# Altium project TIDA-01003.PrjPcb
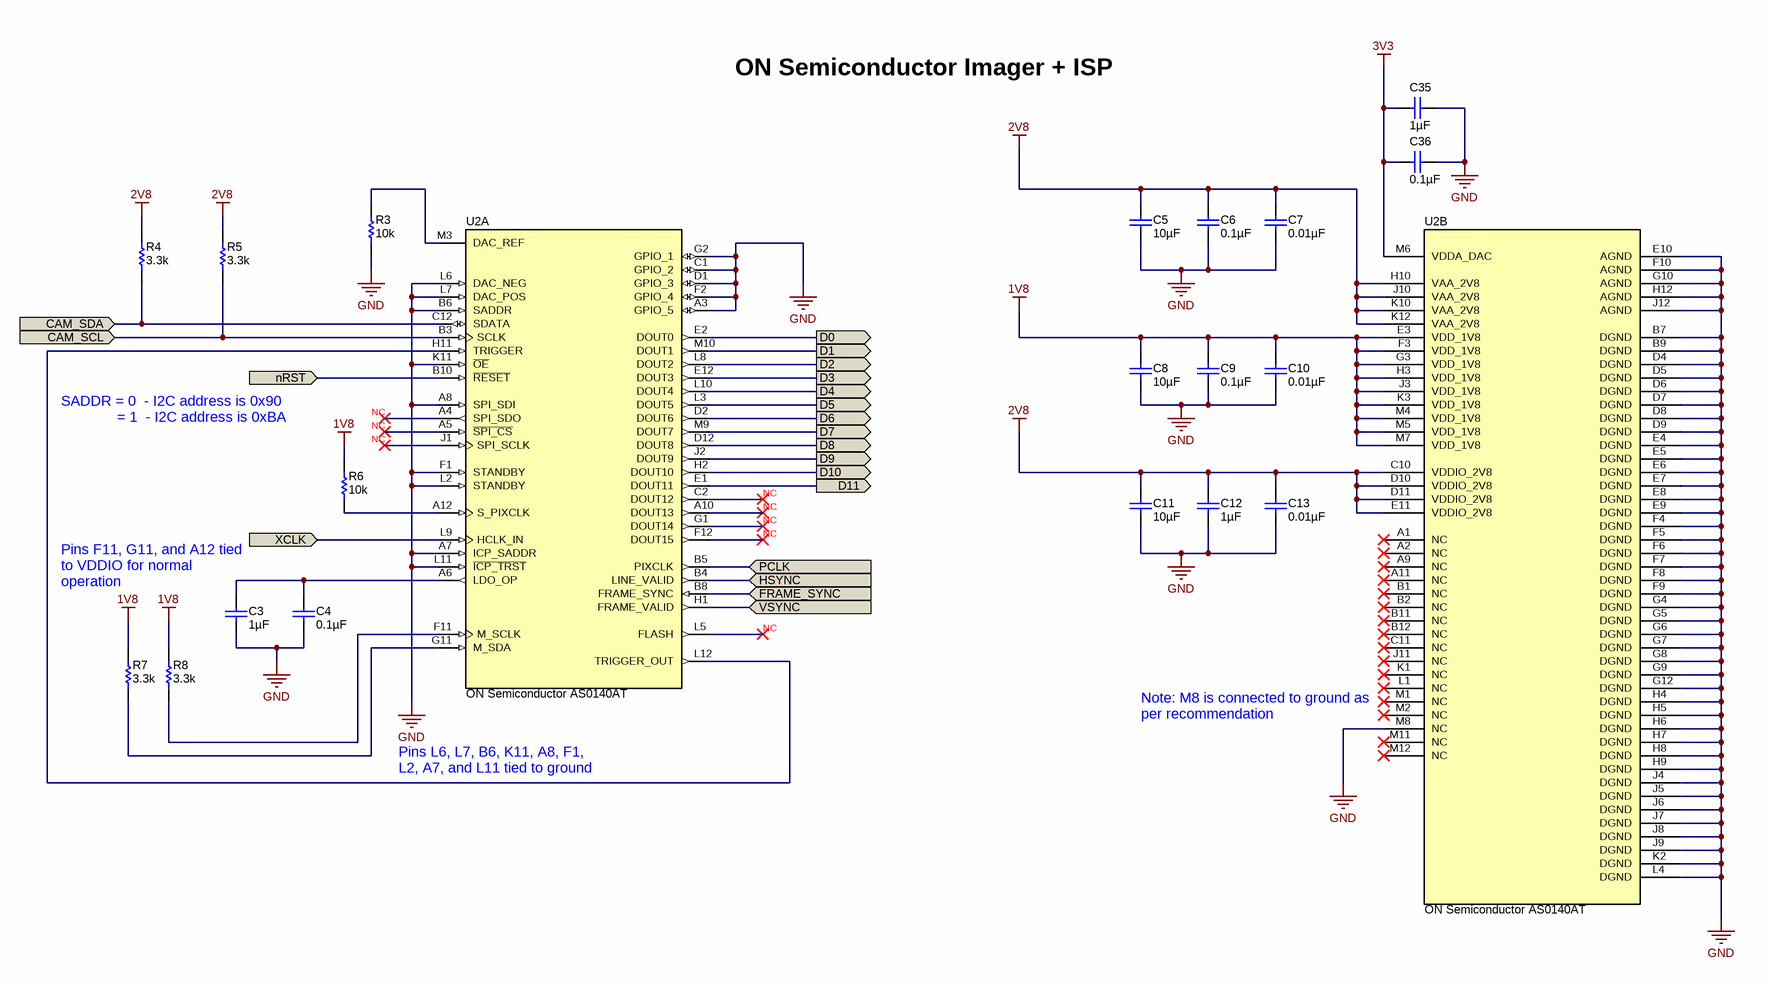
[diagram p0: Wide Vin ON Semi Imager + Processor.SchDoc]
TID: N/A; TechSupport: http://www.ti.com/support; SCH_Rev: E4; PRJ_Title: TIDA-01003-EVM; PRJ_Number: TIDA-01003; PRJ_Engineer: L. CORDOVA; PRJ_Customer: Not Public Release; PCB_Rev: E4; PCB_Layout: L. CORDOVA; CopyrightYear: 2017
5 sheets, 85 parts. Net scope: flat (ports and power ports of the same name join across sheets).
Board file: TIDA-01003.PcbDoc
Sheets:
  Wide Vin ON Semi Imager + Processor.SchDoc
  Wide Vin Power Supply and PoC Filter.SchDoc
  TIDA-01003_EVM_Hardware.SchDoc
  TIDA-01003_CoverSheet.SchDoc
  Wide Vin Serializer.SchDoc

## Sheet Wide Vin ON Semi Imager + Processor.SchDoc
size 431 x 279 mm; Date: Not shown in title block; ApprovedBy: Not shown in title block; CheckedBy: Not shown in title block; Author: Not shown in title block; CompanyName: Not shown in title block; Engineer: Not shown in title block; Organization: Not shown in title block; Address1: Not shown in title block; Address2: Not shown in title block; Address3: Not shown in title block; Address4: Not shown in title block; DocumentNumber: 1; Revision: Use project parameter SCH_Rev; SheetNumber: 4; SheetTotal: 5; PageSetup: Record=PageOptions¦CenterHorizontal=True¦CenterVertical=True¦PrintScale=1.00¦XCorrection=1.00¦YCorrection=1.00¦PrintKind=0¦BorderSize=5000000¦LeftOffset=0¦BottomOffset=0¦Orientation=2¦PaperLength=1000¦PaperWidth=1000¦Scale=100¦PaperSource=15¦PrintQuality=600¦MediaType=1¦DitherType=10¦PaperKind=Letter¦PrintScaleMode=1

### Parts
C3  ValueDisplayed: 1µF  [0402L]  (hidden comment: GRM155R61A105KE15D)
C4  ValueDisplayed: 0.1µF  [0402L]  (hidden comment: GRM155R71C104KA88D)
C5  ValueDisplayed: 10µF  [0805L]  (hidden comment: GRM21BR71A106KE51L)
C6  ValueDisplayed: 0.1µF  [0402L]  (hidden comment: GCM155R71C104KA55D)
C7  ValueDisplayed: 0.01µF  [0402L]  (hidden comment: GRM155R71C103KA01D)
C8  ValueDisplayed: 10µF  [0805L]  (hidden comment: GRM21BR71A106KE51L)
C9  ValueDisplayed: 0.1µF  [0402L]  (hidden comment: GCM155R71C104KA55D)
C10  ValueDisplayed: 0.01µF  [0402L]  (hidden comment: GRM155R71C103KA01D)
C11  ValueDisplayed: 10µF  [0805L]  (hidden comment: GRM21BR71A106KE51L)
C12  ValueDisplayed: 1µF  [0402L]  (hidden comment: GRM155R61A105KE15D)
C13  ValueDisplayed: 0.01µF  [0402L]  (hidden comment: GRM155R71C103KA01D)
C35  ValueDisplayed: 1µF  [0402L]  (hidden comment: GRM155R61A105KE15D)
C36  value 0.1µF  [0402L]  (hidden comment: C1005X7R1E104K050BB)
R3  ValueDisplayed: 10k  [0402L]  (hidden comment: CRCW040210K0JNED)
R4  ValueDisplayed: 3.3k  [0402L]  (hidden comment: CRCW04023K30JNED)
R5  ValueDisplayed: 3.3k  [0402L]  (hidden comment: CRCW04023K30JNED)
R6  ValueDisplayed: 10k  [0402L]  (hidden comment: CRCW040210K0JNED)
R7  ValueDisplayed: 3.3k  [0402L]  (hidden comment: CRCW04023K30JNED)
R8  ValueDisplayed: 3.3k  [0402L]  (hidden comment: CRCW04023K30JNED)
U2  ON Semiconductor AS0140AT  [BGA130_850x850x162]  (parts A,B of 2)

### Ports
CAM_SCL, CAM_SDA, D0 (out), D1 (out), D2 (out), D3 (out), D4 (out), D5 (out), D6 (out), D7 (out), D8 (out), D9 (out), D10 (out), D11 (out), FRAME_SYNC, HSYNC, nRST, PCLK, VSYNC, XCLK

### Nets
1V8: C8.1 C9.1 C10.1 R6.2 R7.2 R8.2 U2.E3(VDD_1V8) U2.F3(VDD_1V8) U2.G3(VDD_1V8) U2.H3(VDD_1V8) U2.J3(VDD_1V8) U2.K3(VDD_1V8) U2.M4(VDD_1V8) U2.M5(VDD_1V8) U2.M7(VDD_1V8)
2V8: C5.1 C6.1 C7.1 C11.1 C12.1 C13.1 R4.2 R5.2 U2.C10(VDDIO_2V8) U2.D10(VDDIO_2V8) U2.D11(VDDIO_2V8) U2.E11(VDDIO_2V8) U2.H10(VAA_2V8) U2.J10(VAA_2V8) U2.K10(VAA_2V8) U2.K12(VAA_2V8)
3V3: C35.1 C36.1 U2.M6(VDDA_DAC)
GND: C3.2 C4.2 C5.2 C6.2 C7.2 C8.2 C9.2 C10.2 C11.2 C12.2 C13.2 C35.2 C36.2 R3.1 U2.A3(GPIO_5) U2.A7(ICP_SADDR) U2.A8(SPI_SDI) U2.B6(SADDR) U2.B7(DGND) U2.B9(DGND) U2.C1(GPIO_2) U2.D1(GPIO_3) U2.D4(DGND) U2.D5(DGND) U2.D6(DGND) U2.D7(DGND) U2.D8(DGND) U2.D9(DGND) U2.E4(DGND) U2.E5(DGND) U2.E6(DGND) U2.E7(DGND) U2.E8(DGND) U2.E9(DGND) U2.E10(AGND) U2.F1(STANDBY) U2.F2(GPIO_4) U2.F4(DGND) U2.F5(DGND) U2.F6(DGND) U2.F7(DGND) U2.F8(DGND) U2.F9(DGND) U2.F10(AGND) U2.G2(GPIO_1) U2.G4(DGND) U2.G5(DGND) U2.G6(DGND) U2.G7(DGND) U2.G8(DGND) U2.G9(DGND) U2.G10(AGND) U2.G12(DGND) U2.H4(DGND) U2.H5(DGND) U2.H6(DGND) U2.H7(DGND) U2.H8(DGND) U2.H9(DGND) U2.H12(AGND) U2.J4(DGND) U2.J5(DGND) U2.J6(DGND) U2.J7(DGND) U2.J8(DGND) U2.J9(DGND) U2.J12(AGND) U2.K2(DGND) U2.K11(~{OE}) U2.L2(STANDBY) U2.L4(DGND) U2.L6(DAC_NEG) U2.L7(DAC_POS) U2.L11(~{ICP_TRST}) U2.M8(NC)
CAM_SCL: R5.1 U2.B3(SCLK) ; port CAM_SCL
CAM_SDA: R4.1 U2.C12(SDATA) ; port CAM_SDA
D0: U2.E2(DOUT0) ; port D0
D1: U2.M10(DOUT1) ; port D1
D2: U2.L8(DOUT2) ; port D2
D3: U2.E12(DOUT3) ; port D3
D4: U2.L10(DOUT4) ; port D4
D5: U2.L3(DOUT5) ; port D5
D6: U2.D2(DOUT6) ; port D6
D7: U2.M9(DOUT7) ; port D7
D8: U2.D12(DOUT8) ; port D8
D9: U2.J2(DOUT9) ; port D9
D10: U2.H2(DOUT10) ; port D10
D11: U2.E1(DOUT11) ; port D11
FRAME_SYNC: U2.B8(FRAME_SYNC) ; port FRAME_SYNC
HSYNC: U2.B4(LINE_VALID) ; port HSYNC
nRST: U2.B10(~{RESET}) ; port nRST
PCLK: U2.B5(PIXCLK) ; port PCLK
VSYNC: U2.H1(FRAME_VALID) ; port VSYNC
XCLK: U2.L9(HCLK_IN) ; port XCLK
NetC3_1: C3.1 C4.1 U2.A6(LDO_OP)
NetR3_2: R3.2 U2.M3(DAC_REF)
NetR6_1: R6.1 U2.A12(S_PIXCLK)
NetR7_1: R7.1 U2.G11(M_SDA)
NetR8_1: R8.1 U2.F11(M_SCLK)
NetU2_H11: U2.H11(TRIGGER) U2.L12(TRIGGER_OUT)

Not connected (* = marked no-connect by the designer): U2 A1(NC)* A2(NC)* A4(SPI_SDO)* A5(~{SPI_CS})* A9(NC)* A10(DOUT13)* A11(NC)* B1(NC)* B2(NC)* B11(NC)* B12(NC)* C2(DOUT12)* C11(NC)* F12(DOUT15)* G1(DOUT14)* J1(SPI_SCLK)* J11(NC)* K1(NC)* L1(NC)* L5(FLASH)* M1(NC)* M2(NC)* M11(NC)* M12(NC)*

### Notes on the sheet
- ON Semiconductor Imager + ISP
- (near R6) SADDR = 0  - I2C address is 0x90
  = 1  - I2C address is 0xBA
- NC
- (near R6) NC
- (near C3) Pins F11, G11, and A12 tied to VDDIO for normal operation
- Note: M8 is connected to ground as per recommendation
- Pins L6, L7, B6, K11, A8, F1, L2, A7, and L11 tied to ground

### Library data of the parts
C3 = GRM155R61A105KE15D: CAP, CERM, 1 µF, 10 V, +/- 10%, X5R, 0402; Manufacturer: MuRata; Polarized: N; CompType: Capacitor; Value: 1uF; U/M: EA; VDC_V: 10; Cap_F: 0.000001; Value1: Unknown; Value2: 10V; TaMin_C: -55; TaMax_C: 85; Cap_Case: 0402; AEC Category: Q200
C4 = GRM155R71C104KA88D: CAP, CERM, 0.1uF, 16V, +/-10%, X7R, 0402; Manufacturer: MuRata; Polarized: N; CompType: Capacitor; U/M: EA; Cap_F: 0.0000001; Tolerance_%: 10; Value1: Unknown; VDC_V: 16; TaMin_C: -55; TaMax_C: 125; Cap_Case: 0402
C5 C8 C11 = GRM21BR71A106KE51L: CAP, CERM, 10uF, 10V, +/-10%, X7R, 0805; Manufacturer: MuRata; Polarized: N; CompType: Capacitor; U/M: EA; Cap_F: 0.00001; Tolerance_%: 10; ESR_Ohm: 0.003; Value1: 0.003 ohm; TaMin_C: -55; TaMax_C: 125; Cap_Case: 0805
C6 C9 = GCM155R71C104KA55D: CAP, CERM, 0.1 µF, 16 V, +/- 10%, X7R, 0402; Manufacturer: MuRata; Value: 0.1uF; VDC_V: 16; Tolerance_%: 10; Polarized: N; CompType: Capacitor; U/M: EA; Cap_F: 0.0000001; Value1: Unknown; Value2: 16V; TaMin_C: -55; TaMax_C: 125; Cap_Case: 0402; SizeArea_mm2: 0.5; SizeAreaWB_mm2: 3; SizeX_mm: 1; SizeZ_mm: 0.6; AEC Category: Q200
C7 C10 C13 = GRM155R71C103KA01D: CAP, CERM, 0.01uF, 16V, +/-10%, X7R, 0402; Manufacturer: MuRata; Polarized: N; CompType: Capacitor; U/M: EA; Cap_F: 0.00000001; Tolerance_%: 10; Value1: Unknown; VDC_V: 16; TaMin_C: -55; TaMax_C: 125; Cap_Case: 0402
C12 C35 = GRM155R61A105KE15D: CAP, CERM, 1 µF, 10 V, +/- 10%, X5R, 0402; Manufacturer: MuRata; Polarized: N; CompType: Capacitor; Value: 1uF; U/M: EA; VDC_V: 10; Cap_F: 0.000001; Value1: Unknown; Value2: 10V; TaMin_C: -55; TaMax_C: 85; Cap_Case: 0402; SizeArea_mm2: 0.5; SizeAreaWB_mm2: 3; SizeX_mm: 1; SizeZ_mm: 0.6; AEC Category: Q200
C36 = C1005X7R1E103K: CAP, CERM, 0.1uF, 25V, +/-10%, X7R, 0402; Manufacturer: TDK Corporation; Tolerance_%: ±10%
R3 R6 = CRCW040210K0JNED: RES, 10 k, 5%, 0.063 W, 0402; Manufacturer: Vishay-Dale; CompType: Resistor; Value: 10k; Res_ohm: 10000; Value_Code: 10k0; Tolerance_%: 5; Power_W: 0.063; Value2: 0.063W; VDC_V: 50; TempCo: 200 ppm/C; EIA_Code: E24; U/M: EA; AEC Category: Q200
R4 R5 R7 R8 = CRCW04023K30JNED: RES, 3.3 k, 5%, 0.063 W, 0402; Manufacturer: Vishay-Dale; CompType: Resistor; Value: 3.3k; Res_ohm: 3300; Value_Code: 3k30; Tolerance_%: 5; Power_W: 0.063; Value2: 0.063W; VDC_V: 50; TempCo: 200 ppm/C; EIA_Code: E24; U/M: EA; AEC Category: Q200
U2 = AS0140: 1MP+ISP Single Package Solution, BGA130; SymbolCreator: Altium

## Sheet Wide Vin Power Supply and PoC Filter.SchDoc
size 431 x 279 mm; Date: Not shown in title block; ApprovedBy: Not shown in title block; CheckedBy: Not shown in title block; Author: Not shown in title block; CompanyName: Not shown in title block; Engineer: Not shown in title block; Organization: Not shown in title block; Address1: Not shown in title block; Address2: Not shown in title block; Address3: Not shown in title block; Address4: Not shown in title block; DocumentNumber: 1; Revision: Use project parameter SCH_Rev; SheetNumber: 2; SheetTotal: 5; PageSetup: Record=PageOptions¦CenterHorizontal=True¦CenterVertical=True¦PrintScale=1.00¦XCorrection=1.00¦YCorrection=1.00¦PrintKind=0¦BorderSize=5000000¦LeftOffset=0¦BottomOffset=0¦Orientation=2¦PaperLength=1000¦PaperWidth=1000¦Scale=100¦PaperSource=15¦PrintQuality=600¦MediaType=1¦DitherType=10¦PaperKind=Letter¦PrintScaleMode=1
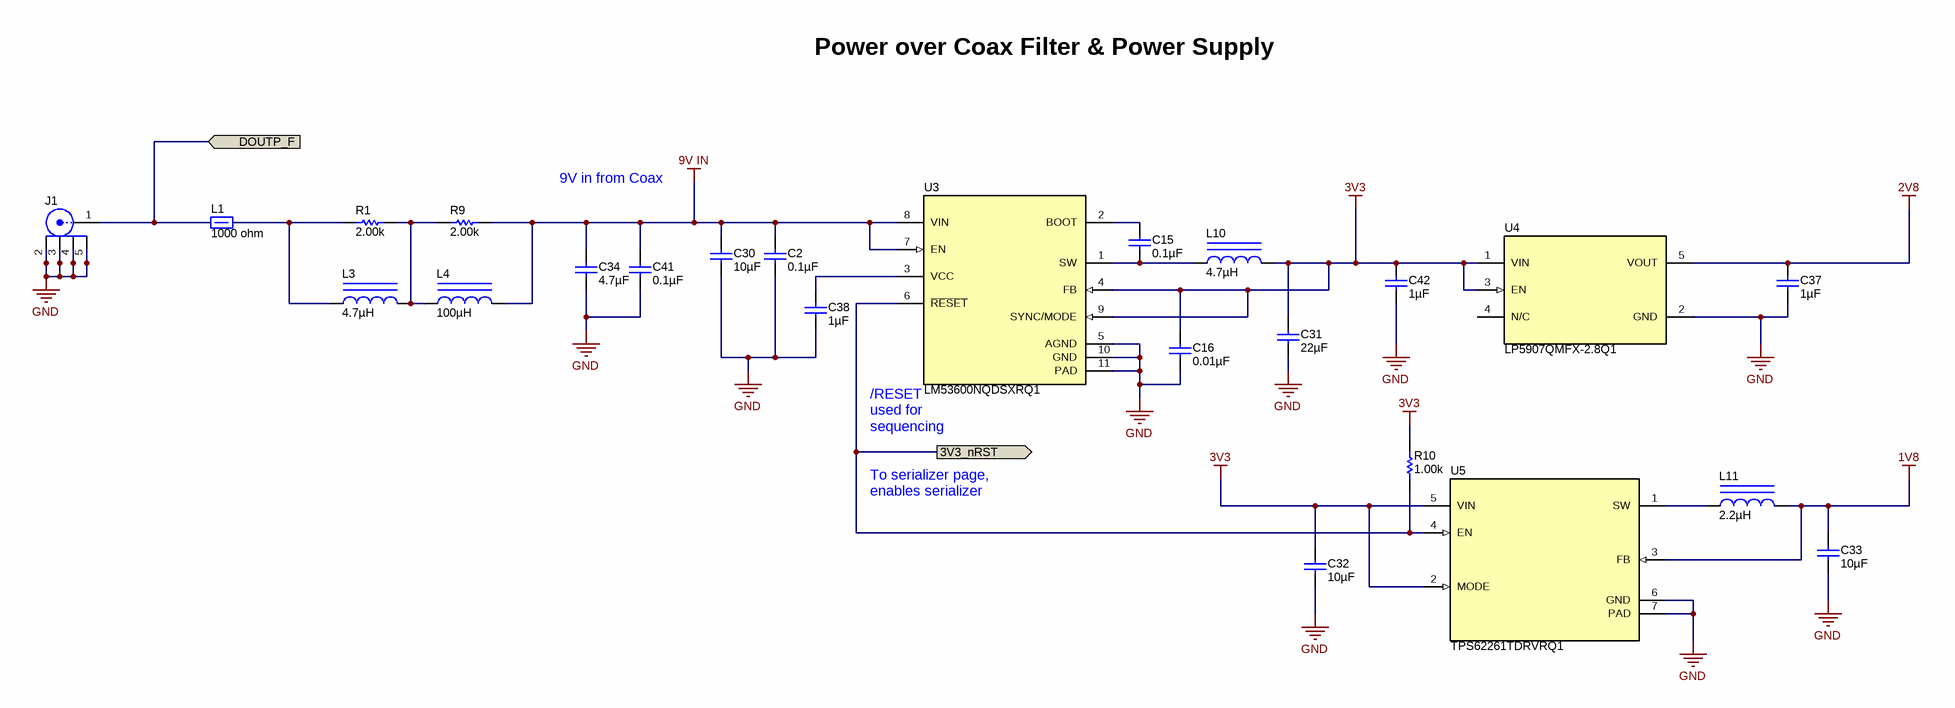
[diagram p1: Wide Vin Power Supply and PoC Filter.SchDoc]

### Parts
C2  ValueDisplayed: 0.1µF  [0402L]  (hidden comment: CGA2B3X7R1H104K050BB)
C15  ValueDisplayed: 0.1µF  [0402L]  (hidden comment: GRM155R71C104KA88D)
C16  ValueDisplayed: 0.01µF  [0402L]  (hidden comment: GRM155R71C103KA01D)
C30  ValueDisplayed: 10µF  [1206_190L]  (hidden comment: CGA5L3X5R1H106K160AB)
C31  ValueDisplayed: 22µF  [0805L]  (hidden comment: CL21B226MQQNNNE)
C32  ValueDisplayed: 10µF  [0805L]  (hidden comment: CL21B106KOQNNNE)
C33  ValueDisplayed: 10µF  [0805L]  (hidden comment: GRM21BR71A106KE51L)
C34  ValueDisplayed: 4.7µF  [0805L]  (hidden comment: CGA4J3X5R1H475M125AB)
C37  ValueDisplayed: 1µF  [0603L]  (hidden comment: LMK107B7105KAHT)
C38  ValueDisplayed: 1µF  [0402L]  (hidden comment: GRM155R61A105KE15D)
C41  ValueDisplayed: 0.1µF  [0402L]  (hidden comment: CGA2B3X7R1H104K050BB)
C42  ValueDisplayed: 1µF  [0603L]  (hidden comment: LMK107B7105KAHT)
J1  59S10H-40ML5-Z  [Rosenberger_59S10H-40ML5-Z]  (value not drawn)
L1  value 1000 ohm  [0402L]  (hidden comment: BLM15AX102SN1D)
L3  ValueDisplayed: 4.7µH  [CBC3225]  (hidden comment: CBC3225T4R7MR)
L4  ValueDisplayed: 100µH  [CBC3225]  (hidden comment: CBC3225T101MR)
L10  ValueDisplayed: 4.7µH  [NRV2010]  (hidden comment: NRV2010T4R7MGF)
L11  ValueDisplayed: 2.2µH  [0805_150]  (hidden comment: MLZ2012M2R2HTD25)
R1  ValueDisplayed: 2.00k  [0402L]  (hidden comment: CRCW04022K00FKED)
R9  ValueDisplayed: 2.00k  [0402L]  (hidden comment: CRCW04022K00FKED)
R10  ValueDisplayed: 1.00k  [0402L]  (hidden comment: CRCW04021K00FKED)
U3  LM53600NQDSXRQ1  [DSX0010A]
U4  LP5907QMFX-2.8Q1  [DBV0005A_N]
U5  TPS62261TDRVRQ1  [DRV0006A]

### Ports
3V3_nRST (out), DOUTP_F

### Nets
1V8: C33.1 L11.2 U5.3(FB)
2V8: C37.1 U4.5(VOUT)
3V3: C16.1 C31.1 C32.1 C42.1 L10.2 R10.2 U3.4(FB) U3.9(SYNC/MODE) U4.1(VIN) U4.3(EN) U5.2(MODE) U5.5(VIN)
9V IN: C2.1 C30.1 C34.1 C41.1 L4.2 R9.1 U3.7(EN) U3.8(VIN)
GND: C2.2 C16.2 C30.2 C31.2 C32.2 C33.2 C34.2 C37.2 C38.2 C41.2 C42.2 J1.2 J1.3 J1.4 J1.5 U3.5(AGND) U3.10(GND) U3.11(PAD) U4.2(GND) U5.6(GND) U5.7(PAD)
3V3_nRST: R10.1 U3.6(~{RESET}) U5.4(EN) ; port 3V3_nRST
DOUTP_F: J1.1 L1.1 ; port DOUTP_F
NetC15_1: C15.1 U3.2(BOOT)
NetC15_2: C15.2 L10.1 U3.1(SW)
NetC38_1: C38.1 U3.3(VCC)
NetL1_2: L1.2 L3.1 R1.2
NetL3_2: L3.2 L4.1 R1.1 R9.2
NetL11_1: L11.1 U5.1(SW)

Not connected (* = marked no-connect by the designer): U4 4(N/C)

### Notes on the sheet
- Power over Coax Filter & Power Supply
- 9V in from Coax
- (near U3) /RESET used for sequencing
- To serializer page, enables serializer

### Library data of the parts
C2 = CGA2B3X7R1H104K050BB: CAP, CERM, 0.1 µF, 50 V, +/- 10%, X7R, AEC-Q200 Grade 1, 0402; Manufacturer: TDK; Value: 0.1uF; VDC_V: 50; Tolerance_%: 10; Polarized: N; CompType: Capacitor; U/M: EA; Cap_F: 0.0000001; Value1: Unknown; Value2: 50V; TaMin_C: -55; TaMax_C: 125; Cap_Case: 0402; AEC Category: Q200; AEC Qualified: Y; AEC Grade: 1
C15 = GRM155R71C104KA88D: CAP, CERM, 0.1 µF, 16 V, +/- 10%, X7R, 0402; Manufacturer: MuRata; Polarized: N; CompType: Capacitor; Value: 0.1uF; U/M: EA; Cap_F: 0.0000001; Tolerance_%: 10; Value1: Unknown; VDC_V: 16; Value2: 16V; TaMin_C: -55; TaMax_C: 125; Cap_Case: 0402; AEC Category: Q200
C16 = GRM155R71C103KA01D: as C7 on sheet Wide Vin ON Semi Imager + Processor
C30 = CGA5L3X5R1H106K160AB: CAP, CERM, 10 µF, 50 V, +/- 10%, X5R, 1206_190; Manufacturer: TDK; Polarized: N; CompType: Capacitor; Value: 10uF; U/M: EA; Cap_F: 0.00001; Tolerance_%: 10; Value1: Unknown; VDC_V: 50; Value2: 50V; TaMin_C: -55; TaMax_C: 85; Cap_Case: 1206; AEC Category: Q200
C31 = CL21B226MQQNNNE: CAP, CERM, 22 µF, 6.3 V, +/- 20%, X7R, 0805; Manufacturer: Samsung Electro-Mechanics; Polarized: N; CompType: Capacitor; Value: 22uF; U/M: EA; Cap_F: 0.000022; Tolerance_%: 20; Value1: Unknown; VDC_V: 6.3; Value2: 6.3V; TaMin_C: -55; TaMax_C: 125; Cap_Case: 0805; AEC Category: Q200; SizeArea_mm2: 2.5; SizeAreaWB_mm2: 6.75; SizeX_mm: 2; SizeY_mm: 1.25; SizeZ_mm: 1.45
C32 = CL21B106KOQNNNE: CAP, CERM, 10 µF, 16 V, +/- 10%, X7R, 0805; Manufacturer: Samsung Electro-Mechanics; Polarized: N; CompType: Capacitor; Value: 10uF; U/M: EA; Cap_F: 0.00001; Tolerance_%: 10; Value1: Unknown; VDC_V: 16; Value2: 16V; TaMin_C: -55; TaMax_C: 125; Cap_Case: 0805; AEC Category: Q200
C33 = GRM21BR71A106KE51L: CAP, CERM, 10 µF, 10 V, +/- 10%, X7R, 0805; Manufacturer: MuRata; Polarized: N; CompType: Capacitor; Value: 10uF; U/M: EA; Cap_F: 0.00001; Tolerance_%: 10; ESR_ohm: 0.003; Value1: 0.003 ohm; Value2: 10V; TaMin_C: -55; TaMax_C: 125; Cap_Case: 0805; AEC Category: Q200
C34 = CGA4J3X5R1H475M125AB: CAP, CERM, 4.7 µF, 50 V, +/- 20%, X5R, AEC-Q200 Grade 3, 0805; Manufacturer: MuRata; Value: 4.7uF; VDC_V: 50; Tolerance_%: 20; Polarized: N; CompType: Capacitor; U/M: EA; Cap_F: 0.0000047; Value1: Unknown; Value2: 50V; TaMin_C: -55; TaMax_C: 85; Cap_Case: 0805; SizeArea_mm2: 2.5; SizeAreaWB_mm2: 6.75; SizeX_mm: 2; SizeY_mm: 1.25; SizeZ_mm: 1.45; AEC Category: Q200; AEC Qualified: Y; AEC Grade: 3
C37 C42 = LMK107B7105KAHT: CAP, CERM, 1 µF, 10 V, +/- 10%, X7R, 0603; Manufacturer: Taiyo Yuden; Polarized: N; CompType: Capacitor; Value: 1uF; U/M: EA; VDC_V: 10; Cap_F: 0.000001; Value1: Unknown; Value2: 10V; TaMin_C: -55; TaMax_C: 125; Cap_Case: 0603; SizeArea_mm2: 1.28; SizeAreaWB_mm2: 4.68; SizeX_mm: 1.6; SizeY_mm: 0.8; SizeZ_mm: 1; AEC Category: Q200; AEC Qualified: Y
C38 = GRM155R61A105KE15D: as C3 on sheet Wide Vin ON Semi Imager + Processor
C41 = CGA2B3X7R1H104K050BB: CAP, CERM, 0.1 µF, 50 V, +/- 10%, X7R, AEC-Q200 Grade 1, 0402; Manufacturer: TDK; Value: 0.1uF; VDC_V: 50; Tolerance_%: 10; Polarized: N; CompType: Capacitor; U/M: EA; Cap_F: 0.0000001; ESR_ohm: 0.039064; Value1: 0.039064 ohm; Value2: 50V; IRMS_A: 0.814669; TaMin_C: -55; TaMax_C: 125; Cap_Case: 0402; SizeArea_mm2: 0.5; SizeAreaWB_mm2: 3; SizeX_mm: 1; SizeZ_mm: 0.6; AEC Category: Q200; AEC Qualified: Y
J1 = 59S10H-40ML5-Z: Connector, HF, 50 Ohm, TH; Manufacturer: Rosenberger; SymbolCreator: X0208326; Gender: Male; ContactFinish: Gold
L1 = BLM15AX102SN1D: Ferrite Bead, 1000 ohm @ 100 MHz, 0.35 A, 0402; Manufacturer: MuRata; Imax_A: 0.35; DCR_ohm: 0.49; Value1: 0.49 ohm; Value2: 0.35A; ZTyp@100MHz_Ohm: 1000
L3 = CBC3225T4R7MR: Inductor, Wirewound, 4.7 µH, 1.01 A, 0.1 ohm, SMD; Manufacturer: Taiyo Yuden; Value: 4.7uH; Ind_H: 4.7E-6; Imax_A: 1.01; Irms: 1.04A @ 40C rise; Isat: 1.25A @ 30% inductance drop; DCR_ohm: 0.1; Value1: 0.1 ohm; Value2: 1.01A; AEC Category: Q200; AEC Qualified: N; SizeAreaWB_mm2: 14.7; SizeArea_mm2: 8; SizeX_mm: 3.2; SizeY_mm: 2.5; SizeZ_mm: 2.7; Green_Lifecycle: Active; Green_REACh: Passed
L4 = CBC3225T101MR: Inductor, Wirewound, 100 µH, 0.27 A, 1.4 ohm, SMD; Manufacturer: Taiyo Yuden; Value: 100uH; Ind_H: 100.0E-6; Imax_A: 0.27; Irms: 0.34A @ 40C rise; Isat: 0.27A @ 30% inductance drop; DCR_ohm: 1.4; Value1: 1.4 ohm; Value2: 0.27A; AEC Category: Q200; AEC Qualified: N; SizeAreaWB_mm2: 14.7; SizeArea_mm2: 8; SizeX_mm: 3.2; SizeY_mm: 2.5; SizeZ_mm: 2.7; Green_Lifecycle: Active; Green_REACh: Passed
L10 = NRV2010T4R7MGF: Inductor, Wirewound, Ferrite, 4.7 µH, 0.76 A, 0.384 ohm, SMD; Manufacturer: Taiyo Yuden; Value: 4.7uH; Ind_H: 4.7E-6; Imax_A: 0.76; Irms: 0.82A @ 40C rise; Isat: 0.76A @ 30% inductance drop; DCR_ohm: 0.384; Value2: 0.76A; AEC Category: Q200
L11 = MLZ2012M2R2HTD25: Inductor, Multilayer, Ferrite, 2.2 µH, 0.4 A, 0.16 ohm, AEC-Q200 Grade 1, SMD; Manufacturer: TDK; Value: 2.2uH; Ind_H: 2.2E-6; Imax_A: 0.4; Irms: 0.6A @ 20C rise; Isat: 0.4A @ 50% inductance drop; DCR_ohm: 0.16; Value2: 0.4A; AEC Category: Q200; AEC Qualified: Y; AEC Grade: 1
R1 R9 = CRCW04022K00FKED: RES, 2.00 k, 1%, 0.063 W, 0402; Manufacturer: Vishay-Dale; CompType: Resistor; Value: 2.00k; Res_ohm: 2000; Value_Code: 2k00; Tolerance_%: 1; Power_W: 0.063; Value2: 0.063W; VDC_V: 50; TempCo: 100 ppm/C; EIA_Code: E96; U/M: EA; AEC Category: Q200
R10 = CRCW04021K00FKED: RES, 1.00 k, 1%, 0.063 W, 0402; Manufacturer: Vishay-Dale; CompType: Resistor; Value: 1.00k; Res_ohm: 1000; Value_Code: 1k00; Tolerance_%: 1; Power_W: 0.063; Value2: 0.063W; VDC_V: 50; TempCo: 100 ppm/C; EIA_Code: E96; U/M: EA; SizeArea_mm2: 0.5; SizeZ_mm: 0.6; AEC Category: Q200
U3 = LM53600NQDSXRQ1: Synchronous Buck Regulator for 650mA Space Constraint Applications, DSX0010A; Manufacturer: Texas Instruments; SymbolCreator: Altium; SizeX_mm: 3; SizeZ_mm: 0.8; CompType: IC; U/M: EA
U4 = LP5907QMFX-2.8Q1: Automotive 250-mA, Ultra-Low-Noise, Low-IQ LDO, DBV0005A (SOT-5); Manufacturer: Texas Instruments; SymbolCreator: a0799628; SizeArea_mm2: 8.12; SizeAreaWB_mm2: 14.82; SizeX_mm: 2.8; SizeY_mm: 2.9; SizeZ_mm: 1.45; CompType: IC; U/M: EA
U5 = TPS62261TDRVRQ1: 2.25-MHz 600-mA STEP-DOWN CONVERTER, DRV0006A; Manufacturer: Texas Instruments; SymbolCreator: Altium; SizeX_mm: 2; SizeZ_mm: 0.8; CompType: IC; U/M: EA

## Sheet TIDA-01003_EVM_Hardware.SchDoc
size 431 x 279 mm; Date: Not shown in title block; ApprovedBy: Not shown in title block; CheckedBy: Not shown in title block; Author: Not shown in title block; CompanyName: Not shown in title block; Engineer: Not shown in title block; Organization: Not shown in title block; Address1: Not shown in title block; Address2: Not shown in title block; Address3: Not shown in title block; Address4: Not shown in title block; DocumentNumber: 1; Revision: Use project parameter SCH_Rev; SheetNumber: 5; SheetTotal: 5; PageSetup: Record=PageOptions¦CenterHorizontal=True¦CenterVertical=True¦PrintScale=1.00¦XCorrection=1.00¦YCorrection=1.00¦PrintKind=0¦BorderSize=5000000¦LeftOffset=0¦BottomOffset=0¦Orientation=2¦PaperLength=1000¦PaperWidth=1000¦Scale=100¦PaperSource=15¦PrintQuality=600¦MediaType=1¦DitherType=10¦PaperKind=Letter¦PrintScaleMode=1
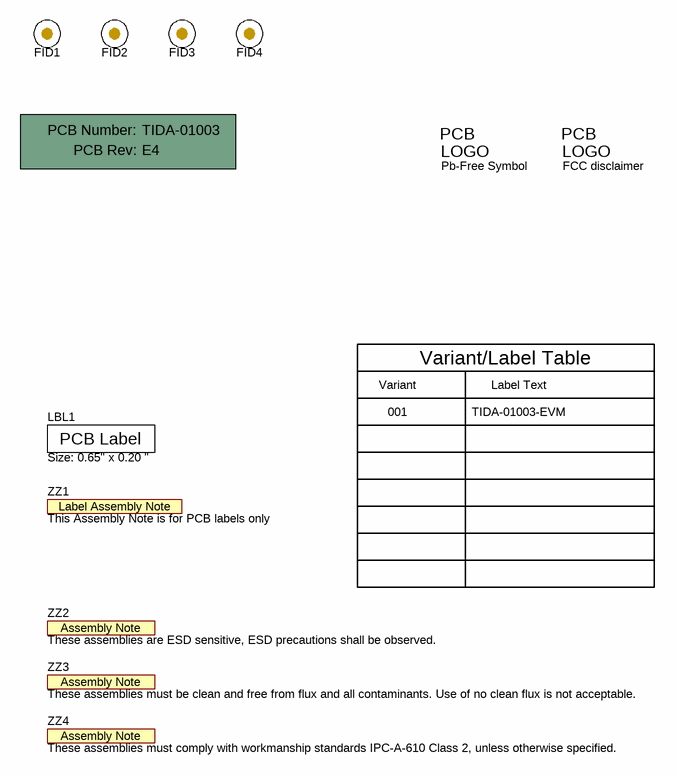
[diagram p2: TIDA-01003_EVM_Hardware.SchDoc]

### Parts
!PCB  Printed Circuit Board  (value not drawn)  (mechanical)
FID1  Fiducial  [Fiducial10-20]  (value not drawn)
FID2  Fiducial  [Fiducial10-20]  (value not drawn)
FID3  Fiducial  [Fiducial10-20]  (value not drawn)
FID4  Fiducial  [Fiducial10-20]  (value not drawn)
LBL1  Size: 0.65" x 0.20 "  [Label_650x200]
Logo2  Pb-Free Symbol  [Pb-Free_Overlay_Small]  (no BOM)
Logo3  FCC disclaimer  [FCC_disclaimer_stacked]  (no BOM)
ZZ1  This Assembly Note is for PCB labels only  [AssemblyNoteLabel]  (no BOM)
ZZ2  These assemblies are ESD sensitive, ESD precautions shall be observed.  [AssemblyNote]  (no BOM)
ZZ3  These assemblies must be clean and free from flux and all contaminants. Use of no clean flux is not acceptable.  [AssemblyNote]  (no BOM)
ZZ4  These assemblies must comply with workmanship standards IPC-A-610 Class 2, unless otherwise specified.  [AssemblyNote]  (no BOM)

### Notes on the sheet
- Variant
- Variant/Label Table
- Label Text
- 001
- TIDA-01003-EVM

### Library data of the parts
!PCB = PCB: Manufacturer: Any; PartNumber: TIDA-01003; SymbolCreator: a0412235
FID1-FID4 = Fiducial: Fiducial mark.  There is nothing to buy or mount.; SymbolCreator: codlsc
LBL1 = THT-14-423-10: Thermal Transfer Printable Labels, 0.650" W x 0.200" H - 10,000 per roll; Manufacturer: Brady; SymbolCreator: a0412235; CompType: Label
Logo2 = Pb-Free: SymbolCreator: a0412235
Logo3 = FCC_disclaimer: SymbolCreator: codlsc
ZZ1 = AssemblyNoteLabel: SymbolCreator: a0412235
ZZ2-ZZ4 = AssemblyNote: SymbolCreator: codlsc

## Sheet TIDA-01003_CoverSheet.SchDoc
size 431 x 279 mm; Date: Not shown in title block; ApprovedBy: Not shown in title block; CheckedBy: Not shown in title block; Author: Not shown in title block; CompanyName: Not shown in title block; Engineer: Not shown in title block; Organization: Not shown in title block; Address1: Not shown in title block; Address2: Not shown in title block; Address3: Not shown in title block; Address4: Not shown in title block; DocumentNumber: 1; Revision: Use project parameter SCH_Rev; SheetNumber: 1; SheetTotal: 5; PageSetup: Record=PageOptions¦CenterHorizontal=True¦CenterVertical=True¦PrintScale=1.00¦XCorrection=1.00¦YCorrection=1.00¦PrintKind=0¦BorderSize=5000000¦LeftOffset=0¦BottomOffset=0¦Orientation=2¦PaperLength=1000¦PaperWidth=1000¦Scale=100¦PaperSource=15¦PrintQuality=600¦MediaType=1¦DitherType=10¦PaperKind=Letter¦PrintScaleMode=1
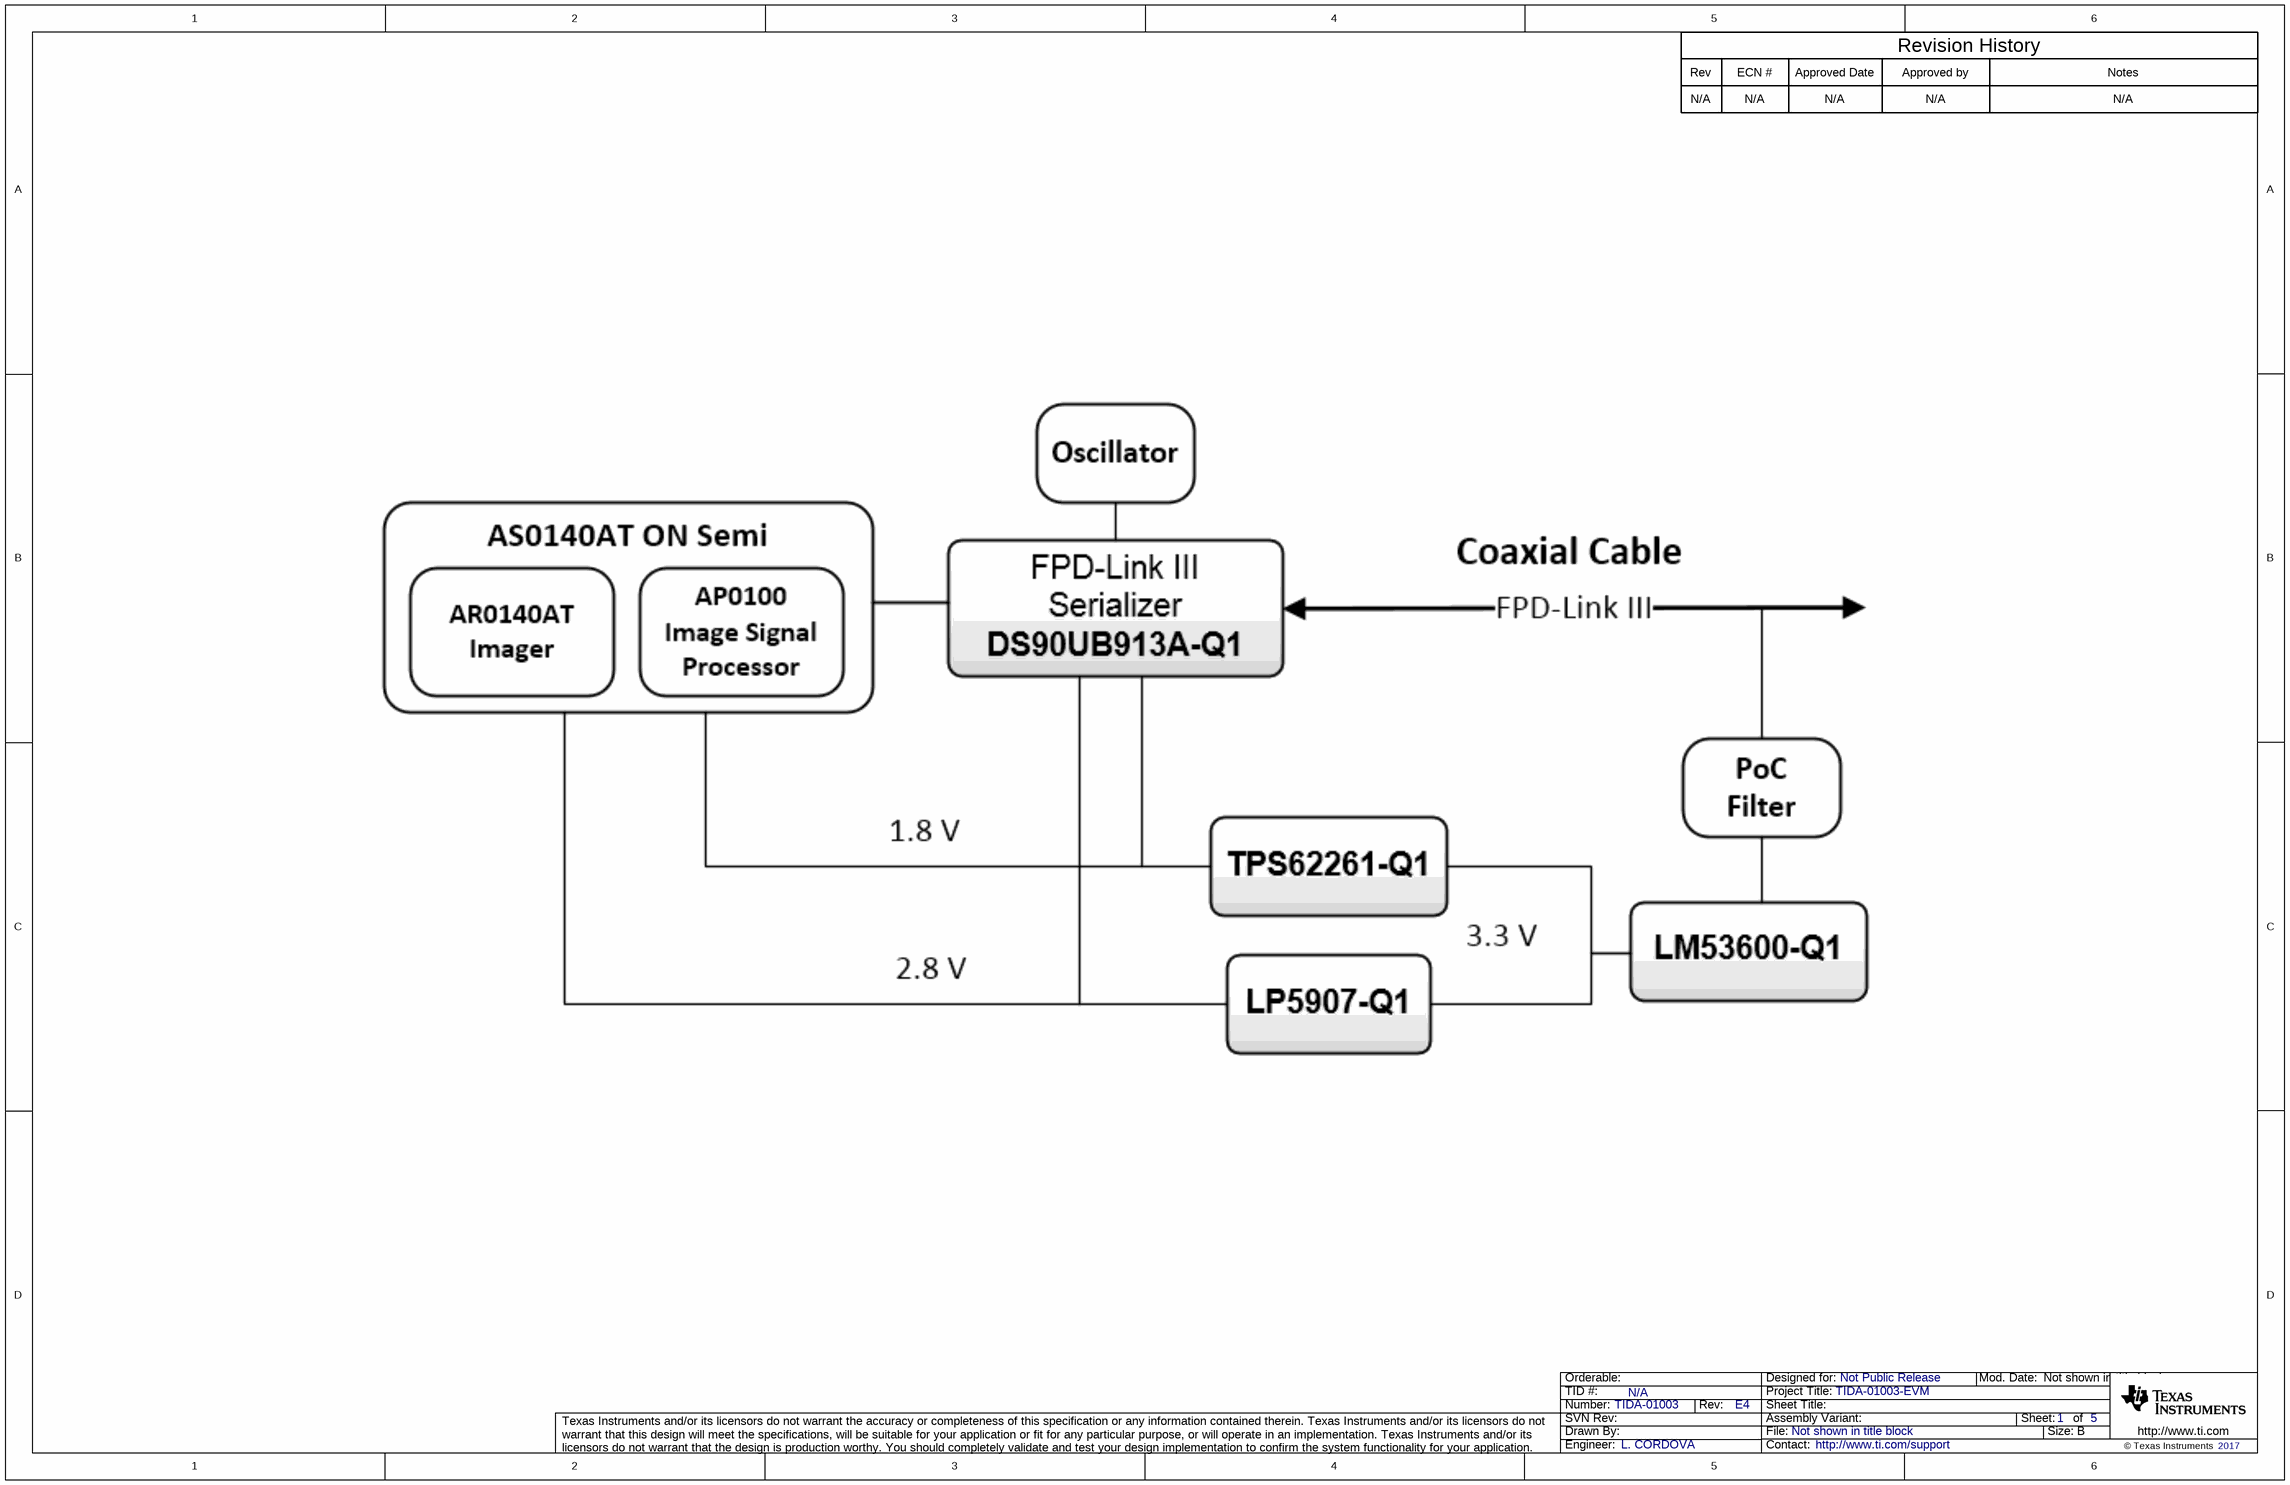
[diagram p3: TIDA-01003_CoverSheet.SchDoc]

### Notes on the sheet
- Rev
- N/A
- ECN #
- Approved Date
- Approved by
- Revision History
- Notes

## Sheet Wide Vin Serializer.SchDoc
size 431 x 279 mm; Date: Not shown in title block; ApprovedBy: Not shown in title block; CheckedBy: Not shown in title block; Author: Not shown in title block; CompanyName: Not shown in title block; Engineer: Not shown in title block; Organization: Not shown in title block; Address1: Not shown in title block; Address2: Not shown in title block; Address3: Not shown in title block; Address4: Not shown in title block; DocumentNumber: 1; Revision: Use project parameter SCH_Rev; SheetNumber: 3; SheetTotal: 5; PageSetup: Record=PageOptions¦CenterHorizontal=True¦CenterVertical=True¦PrintScale=1.00¦XCorrection=1.00¦YCorrection=1.00¦PrintKind=0¦BorderSize=5000000¦LeftOffset=0¦BottomOffset=0¦Orientation=2¦PaperLength=1000¦PaperWidth=1000¦Scale=100¦PaperSource=15¦PrintQuality=600¦MediaType=1¦DitherType=10¦PaperKind=Letter¦PrintScaleMode=1
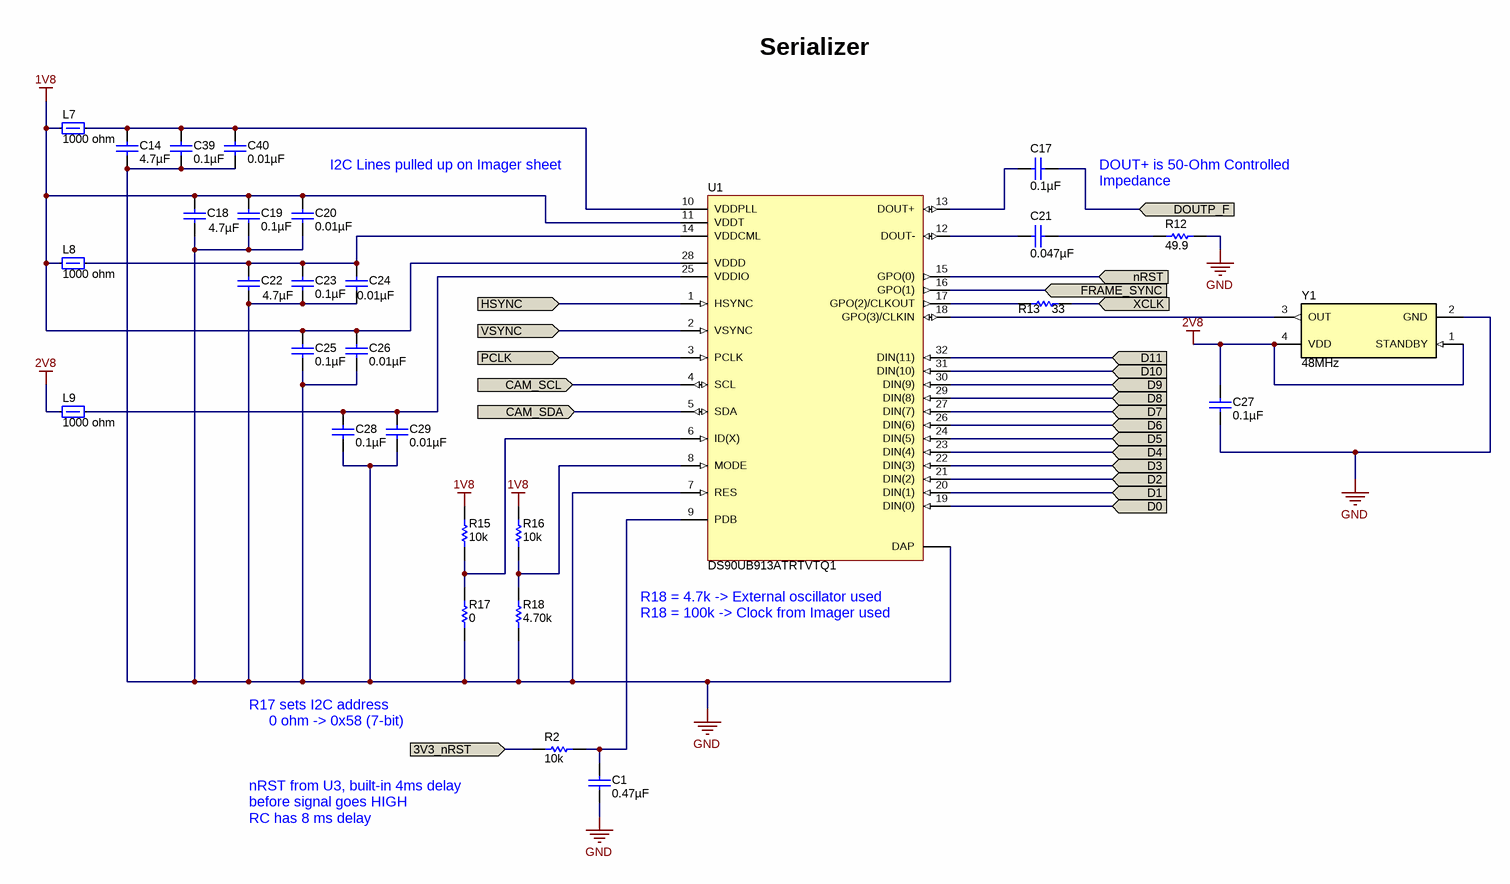
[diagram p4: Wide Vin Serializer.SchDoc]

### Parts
C1  ValueDisplayed: 0.47µF  [0603L]  (hidden comment: C1608X7R1H474K080AC)
C14  ValueDisplayed: 4.7µF  [0603L]  (hidden comment: JMK107BB7475MA-T)
C17  ValueDisplayed: 0.1µF  [0402L]  (hidden comment: CGA2B3X7R1H104K050BB)
C18  value 4.7µF  [0603L]  (hidden comment: CL10B475KQ8NQNC)
C19  ValueDisplayed: 0.1µF  [0402L]  (hidden comment: GRM155R71C104KA88D)
C20  ValueDisplayed: 0.01µF  [0402L]  (hidden comment: GRM155R71C103KA01D)
C21  ValueDisplayed: 0.047µF  [0402L]  (hidden comment: CGA2B3X7R1H473K050BB)
C22  value 4.7µF  [0603L]  (hidden comment: CL10B475KQ8NQNC)
C23  ValueDisplayed: 0.1µF  [0402L]  (hidden comment: GRM155R71C104KA88D)
C24  ValueDisplayed: 0.01µF  [0402L]  (hidden comment: GRM155R71C103KA01D)
C25  ValueDisplayed: 0.1µF  [0402L]  (hidden comment: GRM155R71C104KA88D)
C26  ValueDisplayed: 0.01µF  [0402L]  (hidden comment: GRM155R71C103KA01D)
C27  ValueDisplayed: 0.1µF  [0402L]  (hidden comment: GRM155R71C104KA88D)
C28  ValueDisplayed: 0.1µF  [0402L]  (hidden comment: GRM155R71C104KA88D)
C29  ValueDisplayed: 0.01µF  [0402L]  (hidden comment: GRM155R71C103KA01D)
C39  ValueDisplayed: 0.1µF  [0402L]  (hidden comment: GRM155R71C104KA88D)
C40  ValueDisplayed: 0.01µF  [0402L]  (hidden comment: GRM155R71C103KA01D)
L7  value 1000 ohm  [0402L]  (hidden comment: BLM15AX102SN1D)
L8  value 1000 ohm  [0402L]  (hidden comment: BLM15AX102SN1D)
L9  value 1000 ohm  [0402L]  (hidden comment: BLM15AX102SN1D)
R2  value 10k  [0402L]  (hidden comment: CRCW040210K0JNED)
R12  value 49.9  [0402L]  (hidden comment: CRCW040249R9FKED)
R13  value 33  [0402L]  (hidden comment: CRCW040233R0JNED)
R15  value 10k  [0402L]  (hidden comment: CRCW040210K0JNED)
R16  value 10k  [0402L]  (hidden comment: CRCW040210K0JNED)
R17  value 0  [0402L]  (hidden comment: CRCW04020000Z0ED)
R18  ValueDisplayed: 4.70k  [0402L]  (hidden comment: CRG0402F4K7)
U1  DS90UB913ATRTVTQ1  [RTV0032A]
Y1  Frequency: 48MHz  [Abracon_ASDMB]  (hidden comment: ASDMB-48.000MHZ-LY-T)

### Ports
3V3_nRST (in), CAM_SCL, CAM_SDA, D0, D1, D2, D3, D4, D5, D6, D7, D8, D9, D10, D11, DOUTP_F, FRAME_SYNC, HSYNC, nRST, PCLK, VSYNC, XCLK

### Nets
1V8: C18.1 C19.1 C20.1 C25.1 C26.1 L7.1 L8.1 R15.2 R16.2 U1.11(VDDT) U1.28(VDDD)
2V8: C27.1 L9.1 Y1.1(STANDBY) Y1.4(VDD)
GND: C1.2 C14.2 C18.2 C19.2 C20.2 C22.2 C23.2 C24.2 C25.2 C26.2 C27.2 C28.2 C29.2 C39.2 C40.2 R12.2 R17.1 R18.1 U1.7(RES) U1.33(DAP) Y1.2(GND)
3V3_nRST: R2.2 ; port 3V3_nRST
CAM_SCL: U1.4(SCL) ; port CAM_SCL
CAM_SDA: U1.5(SDA) ; port CAM_SDA
D0: U1.19(DIN(0)) ; port D0
D1: U1.20(DIN(1)) ; port D1
D2: U1.21(DIN(2)) ; port D2
D3: U1.22(DIN(3)) ; port D3
D4: U1.23(DIN(4)) ; port D4
D5: U1.24(DIN(5)) ; port D5
D6: U1.26(DIN(6)) ; port D6
D7: U1.27(DIN(7)) ; port D7
D8: U1.29(DIN(8)) ; port D8
D9: U1.30(DIN(9)) ; port D9
D10: U1.31(DIN(10)) ; port D10
D11: U1.32(DIN(11)) ; port D11
DOUTP_F: C17.1 ; port DOUTP_F
FRAME_SYNC: U1.16(GPO(1)) ; port FRAME_SYNC
HSYNC: U1.1(HSYNC) ; port HSYNC
nRST: U1.15(GPO(0)) ; port nRST
PCLK: U1.3(PCLK) ; port PCLK
VSYNC: U1.2(VSYNC) ; port VSYNC
XCLK: R13.2 ; port XCLK
NetC1_1: C1.1 R2.1 U1.9(PDB)
NetC14_1: C14.1 C39.1 C40.1 L7.2 U1.10(VDDPLL)
NetC17_2: C17.2 U1.13(DOUT+)
NetC21_1: C21.1 R12.1
NetC21_2: C21.2 U1.12(DOUT-)
NetC22_1: C22.1 C23.1 C24.1 L8.2 U1.14(VDDCML)
NetC28_1: C28.1 C29.1 L9.2 U1.25(VDDIO)
NetR13_1: R13.1 U1.17(GPO(2)/CLKOUT)
NetR15_1: R15.1 R17.2 U1.6(ID(X))
NetR16_1: R16.1 R18.2 U1.8(MODE)
NetU1_18: U1.18(GPO(3)/CLKIN) Y1.3(OUT)

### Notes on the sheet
- Serializer
- (near C20) I2C Lines pulled up on Imager sheet
- DOUT+ is 50-Ohm Controlled Impedance
- (near U1) R18 = 4.7k -> External oscillator used
  R18 = 100k -> Clock from Imager used
- R17 sets I2C address
  0 ohm -> 0x58 (7-bit)
- (near R2) nRST from U3, built-in 4ms delay before signal goes HIGH
  RC has 8 ms delay

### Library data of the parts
C1 = C1608X7R1H474K080AC: CAP, CERM, 0.47 µF, 50 V, +/- 10%, X7R, 0603; Manufacturer: TDK; Polarized: N; CompType: Capacitor; Value: 0.47uF; U/M: EA; Cap_F: 0.00000047; Tolerance_%: 10; ESR_ohm: 0.010974; Value1: 0.010974 ohm; VDC_V: 50; Value2: 50V; IRMS_A: 1.57483; TaMin_C: -55; TaMax_C: 125; Cap_Case: 0603; SizeArea_mm2: 1.28; SizeAreaWB_mm2: 4.68; SizeX_mm: 1.6; SizeY_mm: 0.8; SizeZ_mm: 1; AEC Category: Q200
C14 = JMK107BB7475MA-T: CAP, CERM, 4.7 µF, 6.3 V, +/- 10%, X7R, 0603; Manufacturer: Taiyo Yuden; Polarized: N; CompType: Capacitor; Value: 4.7uF; U/M: EA; Cap_F: 0.0000047; Tolerance_%: 10; Value1: Unknown; VDC_V: 6.3; Value2: 6.3V; TaMin_C: -55; TaMax_C: 125; Cap_Case: 0603; AEC Category: Q200
C17 = CGA2B3X7R1H104K050BB: CAP, CERM, 0.1 µF, 50 V, +/- 10%, X7R, AEC-Q200 Grade 1, 0402; Manufacturer: TDK; Polarized: N; CompType: Capacitor; Value: 0.1uF; U/M: EA; Cap_F: 0.0000001; Tolerance_%: 10; ESR_ohm: 0.039064; Value1: 0.039064 ohm; VDC_V: 50; Value2: 50V; IRMS_A: 0.814669; TaMin_C: -55; TaMax_C: 125; Cap_Case: 0402; SizeArea_mm2: 0.5; SizeAreaWB_mm2: 3; SizeX_mm: 1; SizeZ_mm: 0.6; AEC Category: Q200; AEC Qualified: Y
C18 C22 = Capacitor: CAP CER 4.7UF 6.3V 10% X7R 0603; Manufacturer: Samsung Electro-Mechanics America, Inc; Polarized: N; U/M: EA
C19 C23 C25 C27 C28 = GRM155R71C104KA88D: as C4 on sheet Wide Vin ON Semi Imager + Processor
C20 C24 C26 C29 C40 = GRM155R71C103KA01D: as C7 on sheet Wide Vin ON Semi Imager + Processor
C21 = CGA2B3X7R1H473K050BB: CAP, CERM, 0.047 µF, 50 V, +/- 10%, X7R, AEC-Q200 Grade 1, 0402; Manufacturer: TDK; Polarized: N; CompType: Capacitor; Value: 0.047uF; U/M: EA; Cap_F: 0.000000047; Tolerance_%: 10; ESR_ohm: 0.06407; Value1: 0.06407 ohm; VDC_V: 50; Value2: 50V; IRMS_A: 0.646122; TaMin_C: -55; TaMax_C: 125; Cap_Case: 0402; SizeArea_mm2: 0.5; SizeAreaWB_mm2: 3; SizeX_mm: 1; SizeZ_mm: 0.6; AEC Category: Q200; AEC Qualified: Y
C39 = GRM155R71C104KA88D: as C15 on sheet Wide Vin Power Supply and PoC Filter
L7-L9 = BLM15AX102SN1D: as L1 on sheet Wide Vin Power Supply and PoC Filter
R2 R15 R16 = CRCW040210K0JNED: RES, 10k ohm, 5%, 0.063W, 0402; Manufacturer: Vishay-Dale; CompType: Resistor; Res_ohm: 10000; Value_Code: 10k0; Tolerance_%: 5; Power_W: 0.063; VDC_V: 50; TempCo: 200 ppm/C; EIA_Code: E24; U/M: EA
R12 = CRCW040249R9FKED: RES, 49.9 ohm, 1%, 0.063W, 0402; Manufacturer: Vishay-Dale; CompType: Resistor; Value_Code: 49R9; Tolerance_%: 1; Power_W: 0.063; VDC_V: 50; TempCo: 100 ppm/C; EIA_Code: E96; U/M: EA
R13 = CRCW040233R0JNED: RES, 33 ohm, 5%, 0.063W, 0402; Manufacturer: Vishay-Dale; CompType: Resistor; Value_Code: 33R0; Tolerance_%: 5; Power_W: 0.063; VDC_V: 50; TempCo: 200 ppm/C; EIA_Code: E24; U/M: EA
R17 = CRCW04020000Z0ED: RES, 0 ohm, 5%, 0.063W, 0402; Manufacturer: Vishay-Dale; CompType: Resistor; Value_Code: 0000; Tolerance_%: 5; Power_W: 0.063; VDC_V: 50; TempCo: 200 ppm/C; EIA_Code: E24; U/M: EA
R18 = CRG0402F4K7: RES, 4.70 k, 1%, 0.063 W, 0402; Manufacturer: TE Connectivity; CompType: Resistor; Value: 4.70k; Res_ohm: 4700; Value_Code: 4k70; Tolerance_%: 1; Power_W: 0.063; Value2: 0.063W; TempCo: 100 ppm/C; U/M: EA; AEC Category: Q200; AEC Qualified: N
U1 = DS90UB913ATRTVTQ1: DS90UB913A-Q1/DS90UB914A-Q1 25 to 100 MHz 10/20-Bit FPD-Link III Serializer and Deserializer, RTV0032A; Alternate Manufacturer: None; Manufacturer: Texas Instruments; SymbolCreator: x0208325; CompType: IC; U/M: EA
Y1 = ASDMB-48.000MHZ-LY-T: OSC, 48MHz, 1.8 to 3.3V, SMD; Manufacturer: Abracon Corporation; SymbolCreator: Altium; CompType: Oscillator; U/M: EA; TaMin_C: -40; TaMax_C: 85; Frequency Stability: ±10ppm

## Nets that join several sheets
1V8: Wide Vin ON Semi Imager + Processor (15 pins), Wide Vin Power Supply and PoC Filter (C33.1 L11.2 U5.3), Wide Vin Serializer (11 pins)
2V8: Wide Vin ON Semi Imager + Processor (16 pins), Wide Vin Power Supply and PoC Filter (C37.1 U4.5), Wide Vin Serializer (C27.1 L9.1 Y1.1 Y1.4)
3V3: Wide Vin ON Semi Imager + Processor (C35.1 C36.1 U2.M6), Wide Vin Power Supply and PoC Filter (12 pins)
GND: Wide Vin ON Semi Imager + Processor (75 pins), Wide Vin Power Supply and PoC Filter (21 pins), Wide Vin Serializer (21 pins)
3V3_nRST: Wide Vin Power Supply and PoC Filter (R10.1 U3.6 U5.4), Wide Vin Serializer (R2.2)
CAM_SCL: Wide Vin ON Semi Imager + Processor (R5.1 U2.B3), Wide Vin Serializer (U1.4)
CAM_SDA: Wide Vin ON Semi Imager + Processor (R4.1 U2.C12), Wide Vin Serializer (U1.5)
D0: Wide Vin ON Semi Imager + Processor (U2.E2), Wide Vin Serializer (U1.19)
D1: Wide Vin ON Semi Imager + Processor (U2.M10), Wide Vin Serializer (U1.20)
D2: Wide Vin ON Semi Imager + Processor (U2.L8), Wide Vin Serializer (U1.21)
D3: Wide Vin ON Semi Imager + Processor (U2.E12), Wide Vin Serializer (U1.22)
D4: Wide Vin ON Semi Imager + Processor (U2.L10), Wide Vin Serializer (U1.23)
D5: Wide Vin ON Semi Imager + Processor (U2.L3), Wide Vin Serializer (U1.24)
D6: Wide Vin ON Semi Imager + Processor (U2.D2), Wide Vin Serializer (U1.26)
D7: Wide Vin ON Semi Imager + Processor (U2.M9), Wide Vin Serializer (U1.27)
D8: Wide Vin ON Semi Imager + Processor (U2.D12), Wide Vin Serializer (U1.29)
D9: Wide Vin ON Semi Imager + Processor (U2.J2), Wide Vin Serializer (U1.30)
D10: Wide Vin ON Semi Imager + Processor (U2.H2), Wide Vin Serializer (U1.31)
D11: Wide Vin ON Semi Imager + Processor (U2.E1), Wide Vin Serializer (U1.32)
DOUTP_F: Wide Vin Power Supply and PoC Filter (J1.1 L1.1), Wide Vin Serializer (C17.1)
FRAME_SYNC: Wide Vin ON Semi Imager + Processor (U2.B8), Wide Vin Serializer (U1.16)
HSYNC: Wide Vin ON Semi Imager + Processor (U2.B4), Wide Vin Serializer (U1.1)
nRST: Wide Vin ON Semi Imager + Processor (U2.B10), Wide Vin Serializer (U1.15)
PCLK: Wide Vin ON Semi Imager + Processor (U2.B5), Wide Vin Serializer (U1.3)
VSYNC: Wide Vin ON Semi Imager + Processor (U2.H1), Wide Vin Serializer (U1.2)
XCLK: Wide Vin ON Semi Imager + Processor (U2.L9), Wide Vin Serializer (R13.2)

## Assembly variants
001: not fitted C43 FID1 FID2 FID3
